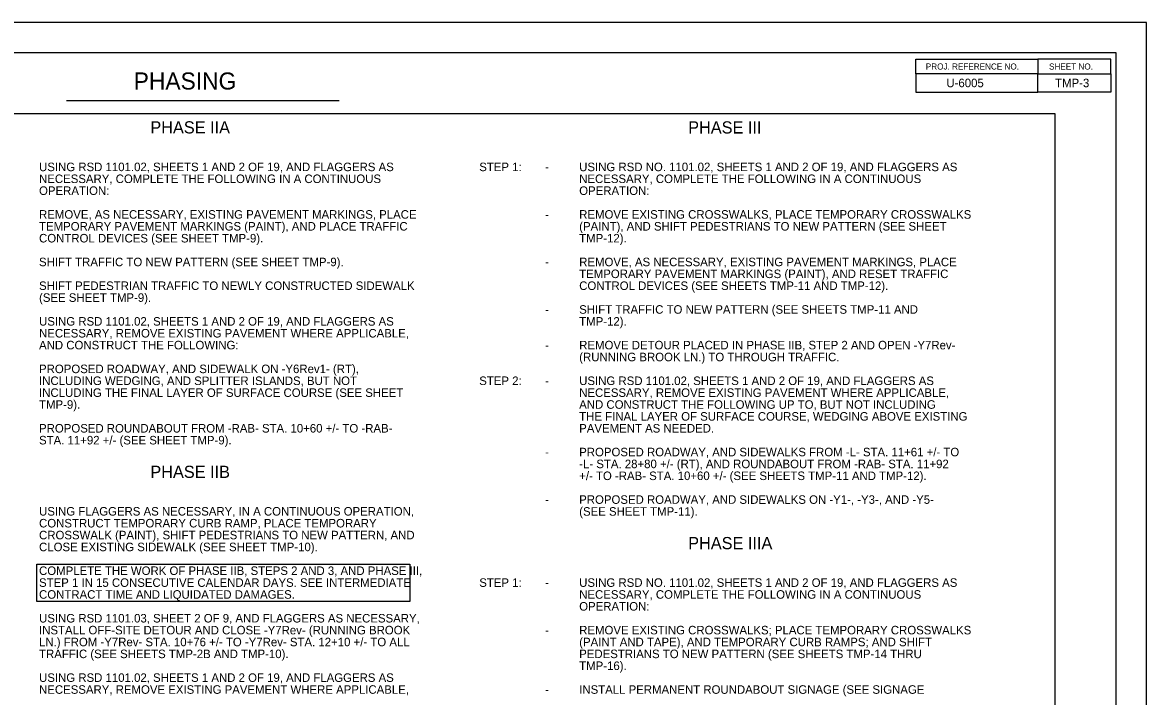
# Model space of a CAD drawing. Extents: x 764226 to 769781, y 650021 to 652521.
# Drawn here: x 767214 to 768137, y 651968 to 652521 of the extents above; entities that cross this region are included whole.
import ezdxf

# ---------------------------------------------------------------- set-up
doc = ezdxf.new("R2010")
doc.units = 0
for name, color, linetype in [('Default', 7, 'Continuous'), ('DEV BORDER CELL', 7, 'Continuous'), ('DEV TRANSPORTATION OPERATIONS PLAN SHEET', 7, 'Continuous'), ('Scratch_Level_0', 7, 'Continuous'), ('Sheet Plot Border Outside CELL', 7, 'Continuous')]:
    doc.layers.add(name, color=color, linetype=linetype)

msp = doc.modelspace()

# ---------------------------------------------------------------- linework, layer by layer
at = {"layer": 'Default'}
msp.add_lwpolyline([(767225.95, 652076.66), (767532.32, 652076.66), (767532.32, 652045.92), (767225.95, 652045.92)], close=True, dxfattribs=at)
at = {"layer": 'DEV BORDER CELL'}
for p, q in [((768047.99, 652479.14), (768107.99, 652479.14)), ((767250.33, 652457.11), (767474.35, 652457.11))]:
    msp.add_line(p, q, dxfattribs=at)
for points in [[(768112.34, 652496.28), (766612.34, 652496.28), (766612.34, 651446.28), (768112.34, 651446.28)], [(767947.99, 652491.14), (768047.99, 652491.14), (768047.99, 652479.14), (767947.99, 652479.14)], [(768047.99, 652479.14), (768107.99, 652479.14), (768107.99, 652491.14), (768047.99, 652491.14)], [(768047.99, 652479.14), (767947.99, 652479.14), (767947.99, 652464.14), (768047.99, 652464.14)], [(768047.99, 652479.14), (768107.99, 652479.14), (768107.99, 652464.14), (768047.99, 652464.14)]]:
    msp.add_lwpolyline(points, close=True, dxfattribs=at)
at = {"layer": 'Scratch_Level_0'}
msp.add_lwpolyline([(768062.34, 652446.28), (766662.34, 652446.28), (766662.34, 651496.28), (767541.19, 651496.28), (767541.19, 651614.55), (768062.34, 651614.55)], close=True, dxfattribs=at)
at = {"layer": 'Sheet Plot Border Outside CELL'}
msp.add_lwpolyline([(766449.34, 651421.28), (768137.34, 651421.28), (768137.34, 652521.28), (766449.34, 652521.28)], close=True, dxfattribs=at)

# ---------------------------------------------------------------- texts
at = {"layer": 'Default'}
for s, height, p in [('PHASE IIA', 10, (767319.27, 652430.19)), ('PHASE III', 10, (767760.94, 652430.14)), ('USING RSD 1101.02, SHEETS 1 AND 2 OF 19, AND FLAGGERS AS ', 7, (767227.87, 652399.22)), ('STEP 1:', 7, (767589.36, 652399.22)), ('USING RSD NO. 1101.02, SHEETS 1 AND 2 OF 19, AND FLAGGERS AS ', 7, (767671.45, 652399.22)), ('NECESSARY, COMPLETE THE FOLLOWING IN A CONTINUOUS ', 7, (767227.87, 652389.46)), ('-', 7, (767643.45, 652399.22)), ('NECESSARY, COMPLETE THE FOLLOWING IN A CONTINUOUS ', 7, (767671.45, 652389.46)), ('OPERATION:', 7, (767227.87, 652379.71)), ('OPERATION:', 7, (767671.45, 652379.71)), ('REMOVE, AS NECESSARY, EXISTING PAVEMENT MARKINGS, PLACE ', 7, (767227.87, 652360.2)), ('REMOVE EXISTING CROSSWALKS, PLACE TEMPORARY CROSSWALKS ', 7, (767671.45, 652360.2)), ('TEMPORARY PAVEMENT MARKINGS (PAINT), AND PLACE TRAFFIC ', 7, (767227.87, 652350.45)), ('-', 7, (767643.45, 652360.2)), ('(PAINT), AND SHIFT PEDESTRIANS TO NEW PATTERN (SEE SHEET ', 7, (767671.45, 652350.45)), ('CONTROL DEVICES (SEE SHEET TMP-9).', 7, (767227.87, 652340.69)), ('TMP-12).', 7, (767671.45, 652340.69)), ('SHIFT TRAFFIC TO NEW PATTERN (SEE SHEET TMP-9).', 7, (767227.87, 652321.18)), ('-', 7, (767643.45, 652321.19)), ('REMOVE, AS NECESSARY, EXISTING PAVEMENT MARKINGS, PLACE ', 7, (767671.45, 652321.19)), ('TEMPORARY PAVEMENT MARKINGS (PAINT), AND RESET TRAFFIC ', 7, (767671.45, 652311.43)), ('SHIFT PEDESTRIAN TRAFFIC TO NEWLY CONSTRUCTED SIDEWALK ', 7, (767227.87, 652301.68)), ('CONTROL DEVICES (SEE SHEETS TMP-11 AND TMP-12).', 7, (767671.45, 652301.68)), ('(SEE SHEET TMP-9).', 7, (767227.87, 652291.92)), ('-', 7, (767643.45, 652282.17)), ('SHIFT TRAFFIC TO NEW PATTERN (SEE SHEETS TMP-11 AND ', 7, (767671.45, 652282.17)), ('USING RSD 1101.02, SHEETS 1 AND 2 OF 19, AND FLAGGERS AS ', 7, (767227.87, 652272.41)), ('TMP-12).', 7, (767671.45, 652272.41)), ('NECESSARY, REMOVE EXISTING PAVEMENT WHERE APPLICABLE, ', 7, (767227.87, 652262.66)), ('AND CONSTRUCT THE FOLLOWING:', 7, (767227.87, 652252.91)), ('-', 7, (767643.45, 652252.91)), ('REMOVE DETOUR PLACED IN PHASE IIB, STEP 2 AND OPEN -Y7Rev- ', 7, (767671.45, 652252.91)), ('(RUNNING BROOK LN.) TO THROUGH TRAFFIC.', 7, (767671.45, 652243.15)), ('PROPOSED ROADWAY, AND SIDEWALK ON -Y6Rev1- (RT), ', 7, (767227.87, 652233.4)), ('INCLUDING WEDGING, AND SPLITTER ISLANDS, BUT NOT ', 7, (767227.87, 652223.64)), ('STEP 2:', 7, (767589.36, 652223.64)), ('USING RSD 1101.02, SHEETS 1 AND 2 OF 19, AND FLAGGERS AS ', 7, (767671.45, 652223.64)), ('INCLUDING THE FINAL LAYER OF SURFACE COURSE (SEE SHEET ', 7, (767227.87, 652213.89)), ('-', 7, (767643.45, 652223.64)), ('NECESSARY, REMOVE EXISTING PAVEMENT WHERE APPLICABLE, ', 7, (767671.45, 652213.89)), ('TMP-9).', 7, (767227.87, 652204.14)), ('AND CONSTRUCT THE FOLLOWING UP TO, BUT NOT INCLUDING ', 7, (767671.45, 652204.14)), ('THE FINAL LAYER OF SURFACE COURSE, WEDGING ABOVE EXISTING ', 7, (767671.45, 652194.38)), ('PROPOSED ROUNDABOUT FROM -RAB- STA. 10+60 +/- TO -RAB- ', 7, (767227.87, 652184.63)), ('PAVEMENT AS NEEDED.', 7, (767671.45, 652184.63)), ('STA. 11+92 +/- (SEE SHEET TMP-9). ', 7, (767227.87, 652174.87)), ('-', 7, (767643.45, 652165.12)), ('PROPOSED ROADWAY, AND SIDEWALKS FROM -L- STA. 11+61 +/- TO ', 7, (767671.45, 652165.12)), ('PHASE IIB', 10, (767319.27, 652147.38)), ('-L- STA. 28+80 +/- (RT), AND ROUNDABOUT FROM -RAB- STA. 11+92 ', 7, (767671.45, 652155.37)), ('+/- TO -RAB- STA. 10+60 +/- (SEE SHEETS TMP-11 AND TMP-12). ', 7, (767671.45, 652145.61)), ('-', 7, (767643.45, 652126.1)), ('PROPOSED ROADWAY, AND SIDEWALKS ON -Y1-, -Y3-, AND -Y5- ', 7, (767671.45, 652126.1)), ('USING FLAGGERS AS NECESSARY, IN A CONTINUOUS OPERATION, ', 7, (767227.87, 652116.46)), ('(SEE SHEET TMP-11).', 7, (767671.45, 652116.35)), ('CONSTRUCT TEMPORARY CURB RAMP, PLACE TEMPORARY ', 7, (767227.87, 652106.71)), ('CROSSWALK (PAINT), SHIFT PEDESTRIANS TO NEW PATTERN, AND ', 7, (767227.87, 652096.96)), ('PHASE IIIA', 10, (767760.94, 652088.86)), ('CLOSE EXISTING SIDEWALK (SEE SHEET TMP-10).', 7, (767227.87, 652087.2)), ('COMPLETE THE WORK OF PHASE IIB, STEPS 2 AND 3, AND PHASE III, ', 7, (767227.87, 652067.69)), ('STEP 1 IN 15 CONSECUTIVE CALENDAR DAYS. SEE INTERMEDIATE ', 7, (767227.87, 652057.94)), ('STEP 1:', 7, (767589.36, 652057.94)), ('USING RSD NO. 1101.02, SHEETS 1 AND 2 OF 19, AND FLAGGERS AS ', 7, (767671.45, 652057.94)), ('CONTRACT TIME AND LIQUIDATED DAMAGES.', 7, (767227.87, 652048.19)), ('-', 7, (767643.45, 652057.94)), ('NECESSARY, COMPLETE THE FOLLOWING IN A CONTINUOUS ', 7, (767671.45, 652048.19)), ('OPERATION:', 7, (767671.45, 652038.43)), ('USING RSD 1101.03, SHEET 2 OF 9, AND FLAGGERS AS NECESSARY, ', 7, (767227.87, 652028.68)), ('INSTALL OFF-SITE DETOUR AND CLOSE -Y7Rev- (RUNNING BROOK ', 7, (767227.87, 652018.92)), ('REMOVE EXISTING CROSSWALKS; PLACE TEMPORARY CROSSWALKS ', 7, (767671.45, 652018.92)), ('LN.) FROM -Y7Rev- STA. 10+76 +/- TO -Y7Rev- STA. 12+10 +/- TO ALL ', 7, (767227.87, 652009.17)), ('-', 7, (767643.45, 652018.92)), ('(PAINT AND TAPE), AND TEMPORARY CURB RAMPS; AND SHIFT ', 7, (767671.45, 652009.17)), ('TRAFFIC (SEE SHEETS TMP-2B AND TMP-10).', 7, (767227.87, 651999.42)), ('PEDESTRIANS TO NEW PATTERN (SEE SHEETS TMP-14 THRU ', 7, (767671.45, 651999.42)), ('TMP-16).', 7, (767671.45, 651989.66)), ('USING RSD 1101.02, SHEETS 1 AND 2 OF 19, AND FLAGGERS AS ', 7, (767227.87, 651979.91)), ('NECESSARY, REMOVE EXISTING PAVEMENT WHERE APPLICABLE, ', 7, (767227.87, 651970.15)), ('-', 7, (767643.45, 651970.15)), ('INSTALL PERMANENT ROUNDABOUT SIGNAGE (SEE SIGNAGE ', 7, (767671.45, 651970.15))]:
    msp.add_text(s, height=height, rotation=359.99991, dxfattribs=at).set_placement(p)
at = {"layer": 'DEV BORDER CELL'}
for s, height, p in [('PROJ. REFERENCE NO.', 4.9992, (767956.1, 652482.64)), ('SHEET NO.', 4.999, (768057.32, 652482.64))]:
    msp.add_text(s, height=height, rotation=0.00056, dxfattribs=at).set_placement(p)
for s, p in [('U-6005', (767972.98, 652468.14)), ('TMP-3', (768062.28, 652468.14))]:
    msp.add_text(s, height=7, dxfattribs=at).set_placement(p)
at = {"layer": 'DEV TRANSPORTATION OPERATIONS PLAN SHEET'}
msp.add_text('PHASING', height=14, dxfattribs=at).set_placement((767305.6, 652466.26))

doc.saveas('drawing.dxf')
